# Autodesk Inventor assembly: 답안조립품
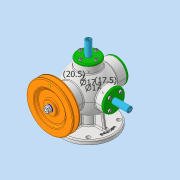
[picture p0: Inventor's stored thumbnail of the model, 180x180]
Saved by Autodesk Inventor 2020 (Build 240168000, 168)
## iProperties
Created: 2021-10
Part Number: 답안조립품
Document SubType Name: Assembly
Designer: user
Author: user
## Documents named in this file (17)
- C:\Users\user\Desktop\611007V1008\답안조립품.iam
- C:\Users\user\Desktop\611007V1008\V-벨트풀리.ipt
- C:\Users\user\Desktop\611007V1008\가변스프링.ipt
- C:\Users\user\Desktop\611007V1008\너트 M8x1.ipt
- C:\Users\user\Desktop\611007V1008\뒤커버.ipt
- C:\Users\user\Desktop\611007V1008\베어링 6202.ipt
- C:\Users\user\Desktop\611007V1008\본체.ipt
- C:\Users\user\Desktop\611007V1008\본체커버.ipt
- C:\Users\user\Desktop\611007V1008\볼트 M4.ipt
- C:\Users\user\Desktop\611007V1008\슬라이드 커버.ipt
- C:\Users\user\Desktop\611007V1008\슬라이드.ipt
- C:\Users\user\Desktop\611007V1008\앞커버.ipt
- C:\Users\user\Desktop\611007V1008\오일 실.ipt
- C:\Users\user\Desktop\611007V1008\와셔 8x17.ipt
- C:\Users\user\Desktop\611007V1008\축.ipt
- C:\Users\user\Desktop\611007V1008\키 4x4.ipt
- C:\Users\user\Desktop\611007V1008\가변스프링2.ipt
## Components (3 placed, 3 different names)
1. V-벨트풀리:1
2. 가변스프링:1
3. 가변스프링2:1
